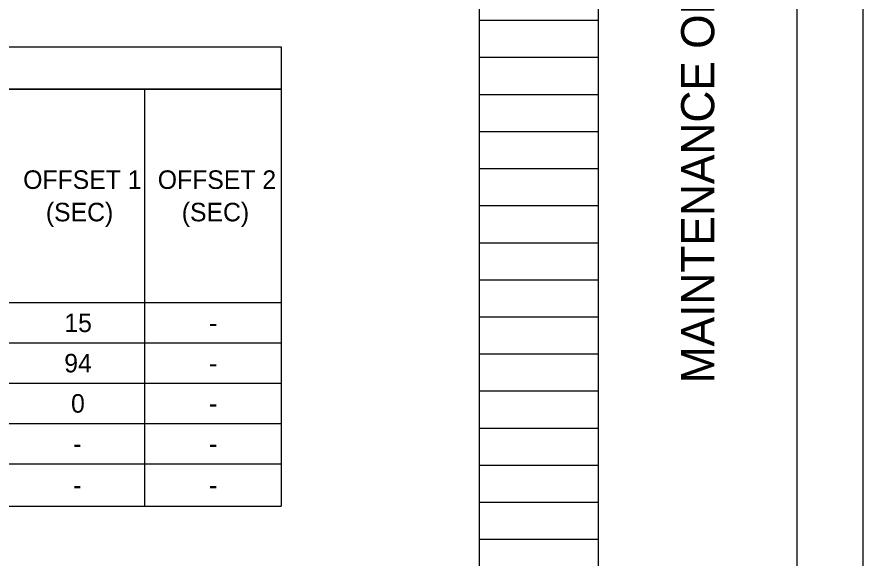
# Model space of a CAD drawing. Extents: x -18.6 to 78.7, y 0 to 36.9.
# Drawn here: x 27.6 to 34, y 6.72 to 10.8 of the extents above; entities that cross this region are included whole.
import ezdxf

# ---------------------------------------------------------------- set-up
doc = ezdxf.new("R2010")
doc.units = 0
for name, color, linetype in [('SH_Border', 7, 'Continuous'), ('SH_Cut_Line', 7, 'Continuous'), ('SH_Data', 7, 'Continuous'), ('SH_Text', 7, 'Continuous')]:
    doc.layers.add(name, color=color, linetype=linetype)

msp = doc.modelspace()

# ---------------------------------------------------------------- linework, layer by layer
at = {"layer": 'SH_Border'}
msp.add_line((32, 0.5), (32, 21.5), dxfattribs=at)
msp.add_lwpolyline([(1.5, 21.5), (33.5, 21.5), (33.5, 0.5), (1.5, 0.5)], close=True, dxfattribs=at)
at = {"layer": 'SH_Cut_Line'}
msp.add_lwpolyline([(0, 0), (34, 0), (34, 22), (0, 22)], close=True, dxfattribs=at)
at = {"layer": 'SH_Data'}
for p, q in [((31.1, 0.98), (31.1, 21.14)), ((32, 0.98), (32, 21.14)), ((31.1, 10.78), (32, 10.78)), ((31.1, 10.5), (32, 10.5)), ((31.1, 10.22), (32, 10.22)), ((31.1, 9.94), (32, 9.94)), ((31.1, 9.66), (32, 9.66)), ((31.1, 9.38), (32, 9.38)), ((31.1, 9.1), (32, 9.1)), ((31.1, 8.82), (32, 8.82)), ((31.1, 8.54), (32, 8.54)), ((31.1, 8.26), (32, 8.26)), ((31.1, 7.98), (32, 7.98)), ((31.1, 7.7), (32, 7.7)), ((31.1, 7.42), (32, 7.42)), ((31.1, 7.14), (32, 7.14)), ((31.1, 6.86), (32, 6.86))]:
    msp.add_line(p, q, dxfattribs=at)
at = {"layer": 'SH_Text'}
for p, q in [((18.7374, 10.5796), (29.6026, 10.5796)), ((29.6026, 10.5796), (29.6026, 7.11)), ((18.7374, 10.26), (29.6026, 10.26)), ((28.5678, 10.26), (28.5678, 7.11)), ((18.7374, 8.647), (29.6026, 8.647)), ((18.7374, 8.3426), (29.6026, 8.3426)), ((18.7374, 8.0383), (29.6026, 8.0383)), ((18.7374, 7.7339), (29.6026, 7.7339)), ((18.7374, 7.4296), (29.6026, 7.4296)), ((18.7374, 7.11), (29.6026, 7.11))]:
    msp.add_line(p, q, dxfattribs=at)
msp.add_lwpolyline([(18.7374, 10.5796), (29.6026, 10.5796), (29.6026, 10.26), (18.7374, 10.26)], close=True, dxfattribs=at)

# ---------------------------------------------------------------- texts
at = {"layer": 'SH_Data'}
msp.add_text('MAINTENANCE OF TRAFFIC - TRAFFIC SIGNAL MODIFICATIONS', height=0.25, rotation=90, dxfattribs=at).set_placement((32.875, 8.0379))
at = {"layer": 'SH_Text'}
for s, p in [('OFFSET 1 ', (27.6517, 9.506)), ('OFFSET 2 ', (28.669, 9.506)), ('(SEC)', (27.823, 9.261)), ('(SEC)', (28.8502, 9.261)), ('15', (27.9628, 8.4248)), ('-', (29.0565, 8.4248)), ('94', (27.9622, 8.1204)), ('-', (29.0565, 8.1204)), ('0', (28.0134, 7.8161)), ('-', (29.0565, 7.8161)), ('-', (28.0294, 7.5118)), ('-', (29.0565, 7.5118)), ('-', (28.0294, 7.1998)), ('-', (29.0565, 7.1998))]:
    msp.add_text(s, height=0.14, dxfattribs=at).set_placement(p)

doc.saveas('drawing.dxf')
